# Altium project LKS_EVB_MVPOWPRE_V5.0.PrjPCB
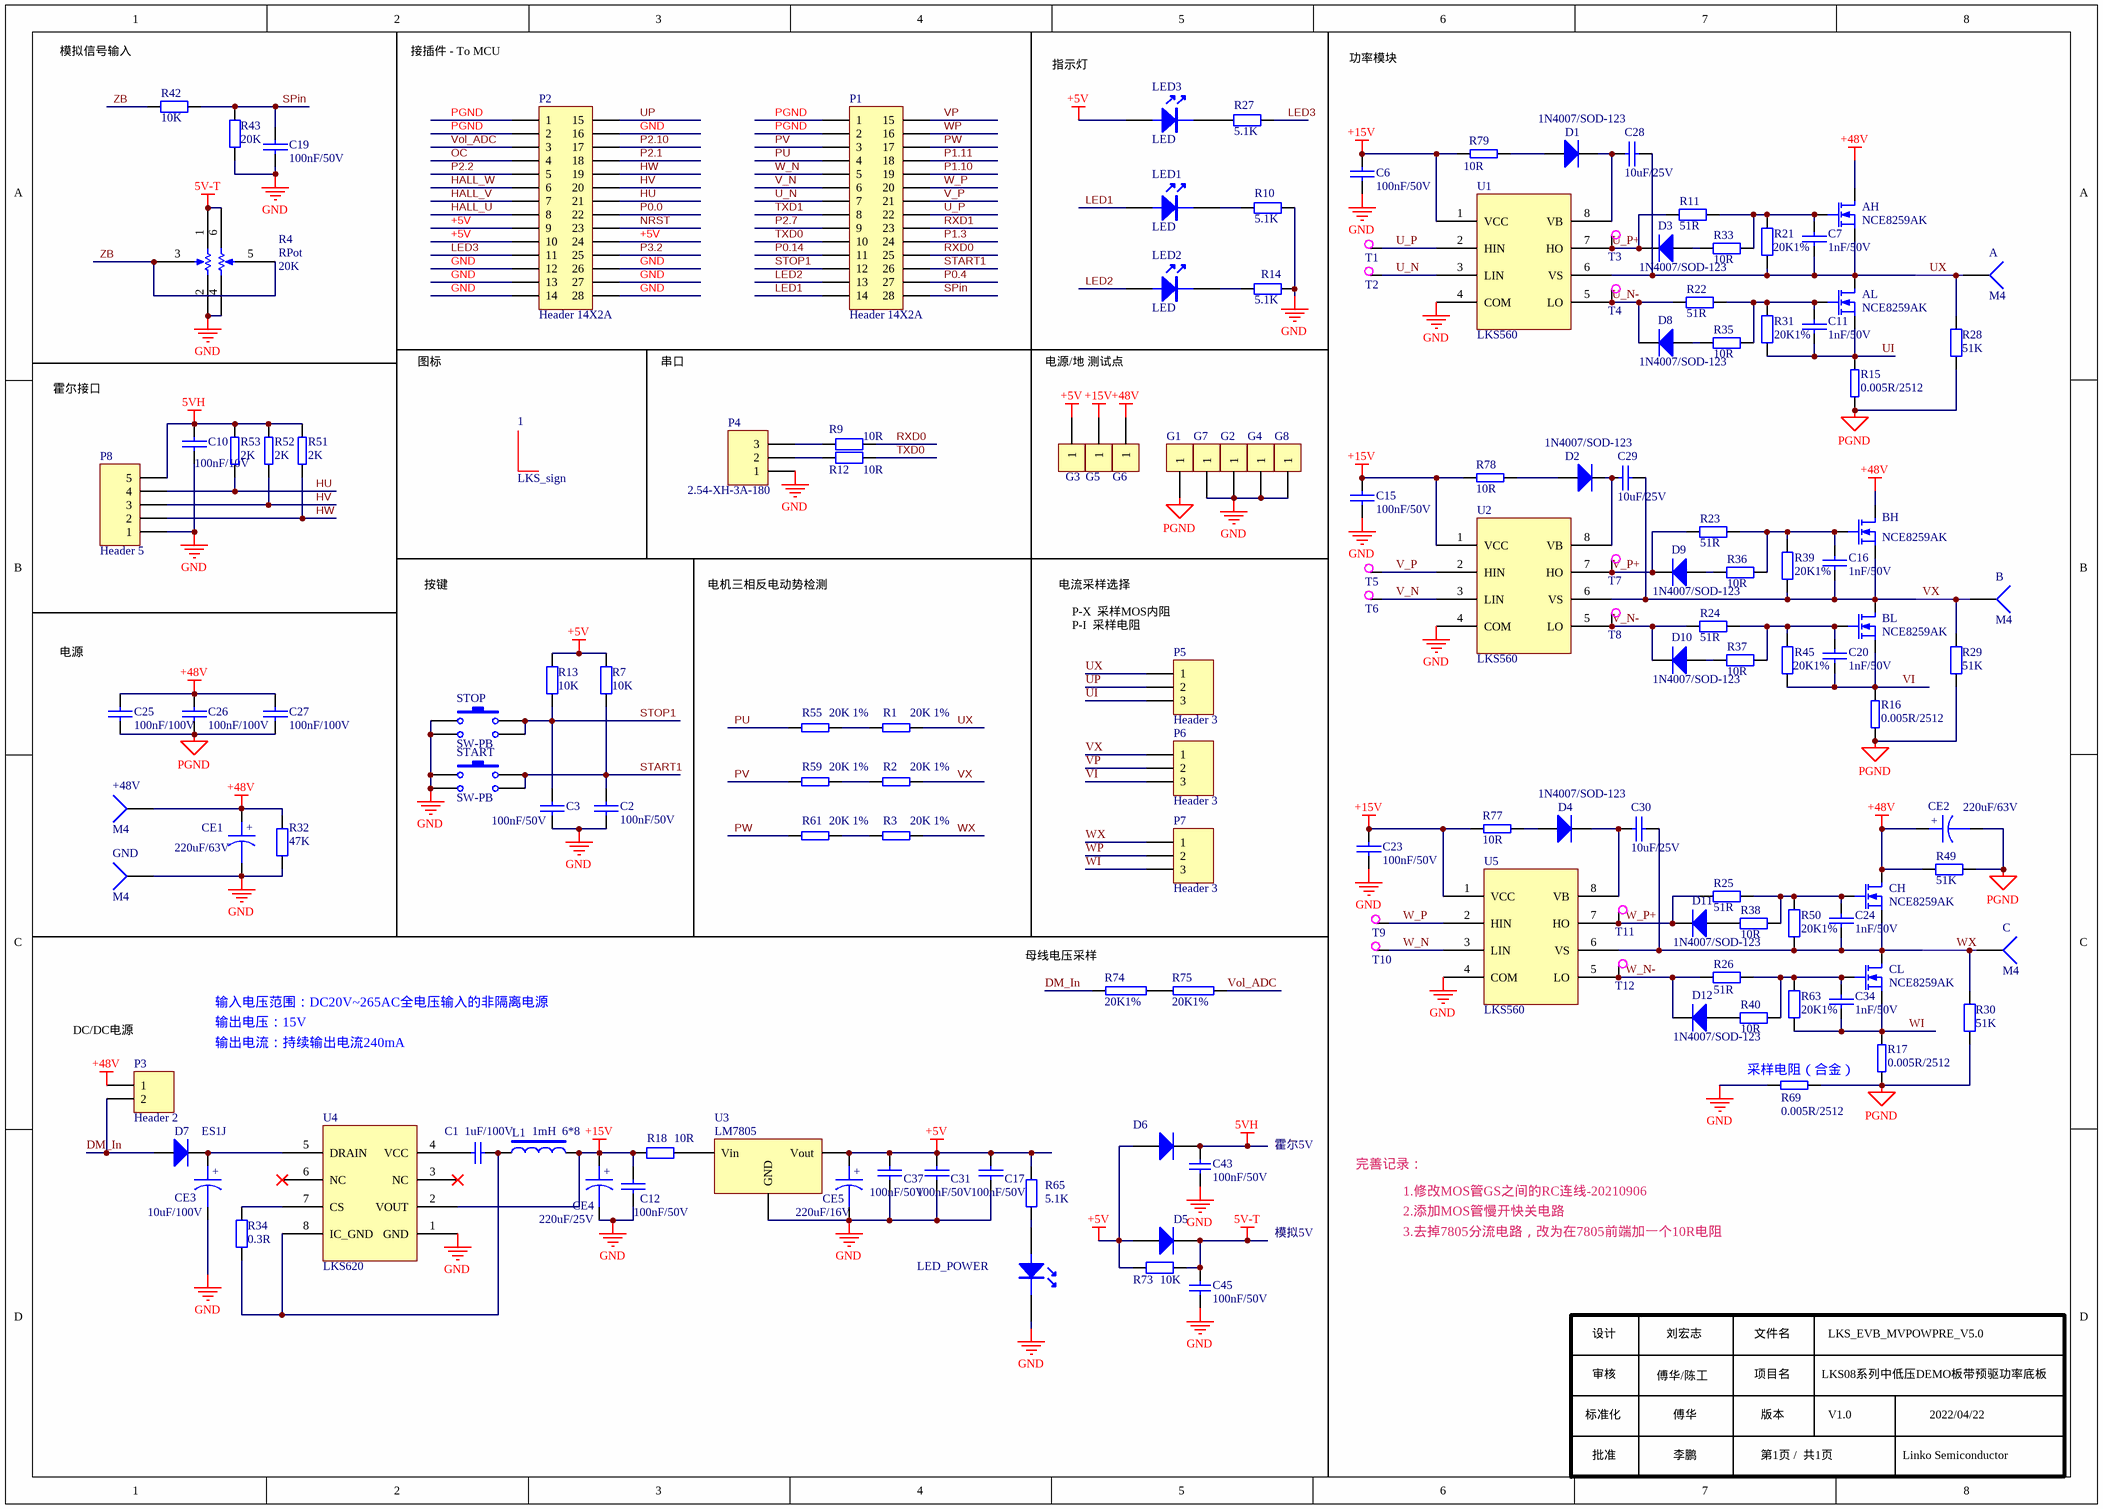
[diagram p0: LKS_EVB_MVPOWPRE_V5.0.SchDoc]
1 sheet, 150 parts. Net scope: global (net labels, ports and power ports of the same name join across sheets).
Board file: LKS_EVB_MVPOWPRE_V5.0.PcbDoc

## Sheet LKS_EVB_MVPOWPRE_V5.0.SchDoc: LKS_DEMO_V4.0
size A3; Author: LKS_LHZ

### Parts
1  LKS_sign  [LKS_LOGO2]
+48V  M4  [M4_CONECTOR]
A  M4  [M4_Conector]
AH  NCE8259AK  [TO-252]
AL  NCE8259AK  [TO-252]
B  M4  [M4_Conector]
BH  NCE8259AK  [TO-252]
BL  NCE8259AK  [TO-252]
C  M4  [M4_Conector]
C1  1uF/100V  [1206]
C2  100nF/50V  [0603C]
C3  100nF/50V  [0603C]
C6  100nF/50V  [0603C]
C7  1nF/50V  [0603C]
C10  100nF/10V  [0603C]
C11  1nF/50V  [0603C]
C12  100nF/50V  [0603C]
C15  100nF/50V  [0603C]
C16  1nF/50V  [0603C]
C17  100nF/50V  [0603C]
C19  100nF/50V  [0603C]
C20  1nF/50V  [0603C]
C23  100nF/50V  [0603C]
C24  1nF/50V  [0603C]
C25  100nF/100V  [0805C]
C26  100nF/100V  [0805C]
C27  100nF/100V  [0805C]
C28  10uF/25V  [1206C]
C29  10uF/25V  [1206C]
C30  10uF/25V  [1206C]
C31  100nF/50V  [0603C]
C34  1nF/50V  [0603C]
C37  100nF/50V  [0603C]
C43  100nF/50V  [0603C]
C45  100nF/50V  [0603C]
CE1  220uF/63V  [220UF/63V 12.5*12.5]
CE2  220uF/63V  [220UF/63V 12.5*12.5]
CE3  10uF/100V  [220UF/25V 8*10]
CE4  220uF/25V  [220UF/25V 8*10]
CE5  220uF/16V  [220UF/25V 8*10]
CH  NCE8259AK  [TO-252]
CL  NCE8259AK  [TO-252]
D1  1N4007/SOD-123  [SOD123]
D2  1N4007/SOD-123  [SOD123]
D3  1N4007/SOD-123  [SOD123]
D4  1N4007/SOD-123  [SOD123]
D5  1N4007  [D1206]  (value not drawn)
D6  1N4007  [D1206]  (value not drawn)
D7  ES1J  [DO-214AC]
D8  1N4007/SOD-123  [SOD123]
D9  1N4007/SOD-123  [SOD123]
D10  1N4007/SOD-123  [SOD123]
D11  1N4007/SOD-123  [SOD123]
D12  1N4007/SOD-123  [SOD123]
G1  PAD1.2  [PAD1.2]  (value not drawn)
G2  PAD1.2  [PAD1.2]  (value not drawn)
G3  PAD1.2  [PAD1.2]  (value not drawn)
G4  PAD1.2  [PAD1.2]  (value not drawn)
G5  PAD1.2  [PAD1.2]  (value not drawn)
G6  PAD1.2  [PAD1.2]  (value not drawn)
G7  PAD1.2  [PAD1.2]  (value not drawn)
G8  PAD1.2  [PAD1.2]  (value not drawn)
GND  M4  [M4_CONECTOR]
L1  1mH  6*8  [L_DIP_6*8MM]
LED1  LED  [SOD323]
LED2  LED  [SOD323]
LED3  LED  [SOD323]
LED_POWER  LED_R  [SOD323]  (value not drawn)
P1  Header 14X2A  [HDR2X14_CEN]
P2  Header 14X2A  [HDR2X14_CEN]
P3  Header 2  [HDR1X2]
P4  2.54-XH-3A-180  [2.54-XH-3A-180]
P5  Header 3  [HDR1X3]
P6  Header 3  [HDR1X3]
P7  Header 3  [HDR1X3]
P8  Header 5  [2.54-XH-5A-180]
R1  20K 1%  [0805R]
R2  20K 1%  [0805R]
R3  20K 1%  [0805R]
R4  RPot  value 20K  [RK097-W-1]
R7  10K  [0603R]
R9  10R  [0603R]
R10  5.1K  [0603R]
R11  51R  [0805R]
R12  10R  [0603R]
R13  10K  [0603R]
R14  5.1K  [0603R]
R15  0.005R/2512  [2512]
R16  0.005R/2512  [2512]
R17  0.005R/2512  [2512]
R18  10R  [1206R]
R21  20K1%  [0603R]
R22  51R  [0805R]
R23  51R  [0805R]
R24  51R  [0805R]
R25  51R  [0805R]
R26  51R  [0805R]
R27  5.1K  [0603R]
R28  51K  [0805R]
R29  51K  [0805R]
R30  51K  [0805R]
R31  20K1%  [0603R]
R32  47K  [1206R]
R33  10R  [0805R]
R34  0.3R  [1206]
R35  10R  [0805R]
R36  10R  [0805R]
R37  10R  [0805R]
R38  10R  [0805R]
R39  20K1%  [0603R]
R40  10R  [0805R]
R42  10K  [0603R]
R43  20K  [0603R]
R45  20K1%  [0603R]
R49  51K  [0805R]
R50  20K1%  [0603R]
R51  2K  [0805R]
R52  2K  [0805R]
R53  2K  [0805R]
R55  20K 1%  [0805R]
R59  20K 1%  [0805R]
R61  20K 1%  [0805R]
R63  20K1%  [0603R]
R65  5.1K  [0603R]
R69  0.005R/2512  [2512]
R73  10K  [0603R]
R74  20K1%  [0603R]
R75  20K1%  [0603R]
R77  10R  [0805r]
R78  10R  [0805r]
R79  10R  [0805r]
START  SW-PB  [SW-PB  12*12]
STOP  SW-PB  [SW-PB  12*12]
T1  TestP  [TP-80]  (value not drawn)
T2  TestP  [TP-80]  (value not drawn)
T3  TestP  [TP-80]  (value not drawn)
T4  TestP  [TP-80]  (value not drawn)
T5  TestP  [TP-80]  (value not drawn)
T6  TestP  [TP-80]  (value not drawn)
T7  TestP  [TP-80]  (value not drawn)
T8  TestP  [TP-80]  (value not drawn)
T9  TestP  [TP-80]  (value not drawn)
T10  TestP  [TP-80]  (value not drawn)
T11  TestP  [TP-80]  (value not drawn)
T12  TestP  [TP-80]  (value not drawn)
U1  LKS560  [SO-8]
U2  LKS560  [SO-8]
U3  LM7805  [SOT-89]
U4  LKS620  [SO-8]
U5  LKS560  [SO-8]

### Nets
5V-T: C45.2 D5.2(K) R4.1(TOP) R4.6(TOP) R73.2
5VH: C10.1 C43.2 D6.2(K) P8.5 R51.2 R52.2 R53.2
+5V: C17.2 C31.2 C37.2 CE5.1 D5.1(A) D6.1(A) G3.1 LED3.1(A) P2.9 P2.10 P2.24 R7.1 R13.2 R65.1 R73.1 U3.1(Vout)
+15V: C6.2 C12.1 C15.2 C23.2 CE4.1 G5.1 L1.1 R18.1 R77.1 R78.1 R79.1 U1.1(VCC) U2.1(VCC) U4.2(VOUT) U5.1(VCC)
+48V: +48V.1 AH.2(D) BH.2(D) C25.2 C26.2 C27.2 CE1.1 CE2.1 CH.2(D) G6.1 P3.1 R32.1 R49.1
GND: C2.1 C3.2 C6.1 C10.2 C12.2 C15.1 C17.1 C19.1 C23.1 C31.1 C37.1 C43.1 C45.1 CE1.2 CE3.2 CE4.2 CE5.2 G2.1 G4.1 G7.1 G8.1 GND.1 LED_POWER.2(K) P2.12 P2.13 P2.14 P2.16 P2.26 P2.27 P2.28 P4.1 P8.1 R4.2(TAP) R4.4(BOT) R10.2 R14.2 R32.2 R43.1 R69.2 START.1 START.3 STOP.1 STOP.3 U1.4(COM) U2.4(COM) U3.2(GND) U4.1(GND) U5.4(COM)
PGND: C25.1 C26.1 C27.1 CE2.2 G1.1 P1.1 P1.2 P2.1 P2.2 R15.2 R16.1 R17.2 R28.1 R29.1 R30.1 R49.2 R69.1
DM_In: D7.1(A) P3.2 R74.1
HALL_U: P2.8
HALL_V: P2.7
HALL_W: P2.6
HU: P2.21 P8.4 R53.1
HV: P2.20 P8.3 R52.1
HW: P2.19 P8.2 R51.1
LED1: LED1.1(A) P1.14
LED2: LED2.1(A) P1.13
LED3: P2.11 R27.2
NRST: P2.23
OC: P2.4
P0.0: P2.22
P0.4: P1.27
P0.14: P1.11
P1.3: P1.24
P1.10: P1.19
P1.11: P1.18
P2.1: P2.18
P2.2: P2.5
P2.7: P1.9
P2.10: P2.17
P3.2: P2.25
PU: P1.4 R55.1
PV: P1.3 R59.1
PW: P1.17 R61.1
RXD0: P1.25 R9.1
RXD1: P1.23
SPin: C19.2 P1.28 R42.2 R43.2
START1: C2.2 P1.26 R7.2 START.2 START.4
STOP1: C3.1 P1.12 R13.1 STOP.2 STOP.4
TXD0: P1.10 R12.2
TXD1: P1.8
U_N: P1.7 T2.1 U1.3(LIN)
U_N-: D8.2(K) R22.2 T4.1 U1.5(LO)
U_P: P1.22 T1.1 U1.2(HIN)
U_P+: D3.2(K) R11.1 T3.1 U1.7(HO)
UI: AL.3(S) C11.2 P5.3 R15.1 R31.1
UP: P2.15 P5.2
UX: A.1 AH.3(S) AL.2(D) C7.2 C28.2 P5.1 R1.2 R21.1 R28.2 U1.6(VS)
V_N: P1.6 T6.1 U2.3(LIN)
V_N-: D10.2(K) R24.2 T8.1 U2.5(LO)
V_P: P1.21 T5.1 U2.2(HIN)
V_P+: D9.2(K) R23.1 T7.1 U2.7(HO)
VI: BL.3(S) C20.2 P6.3 R16.2 R45.1
Vol_ADC: P2.3 R75.2
VP: P1.15 P6.2
VX: B.1 BH.3(S) BL.2(D) C16.2 C29.2 P6.1 R2.2 R29.2 R39.1 U2.6(VS)
W_N: P1.5 T10.1 U5.3(LIN)
W_N-: D12.2(K) R26.2 T12.1 U5.5(LO)
W_P: P1.20 T9.1 U5.2(HIN)
W_P+: D11.2(K) R25.1 T11.1 U5.7(HO)
WI: C34.2 CL.3(S) P7.3 R17.1 R63.1
WP: P1.16 P7.2
WX: C.1 C24.2 C30.2 CH.3(S) CL.2(D) P7.1 R3.2 R30.2 R50.1 U5.6(VS)
ZB: R4.3(BOT) R4.5(TAP) R42.1
NetAH_1: AH.1(G) C7.1 R11.2 R21.2 R33.2
NetAL_1: AL.1(G) C11.1 R22.1 R31.2 R35.2
NetBH_1: BH.1(G) C16.1 R23.2 R36.2 R39.2
NetBL_1: BL.1(G) C20.1 R24.1 R37.2 R45.2
NetC1_1: C1.1 U4.4(VCC)
NetC1_2: C1.2 L1.2 R34.2 U4.8(IC_GND)
NetC24_1: C24.1 CH.1(G) R25.2 R38.2 R50.2
NetC28_1: C28.1 D1.2(K) U1.8(VB)
NetC29_1: C29.1 D2.2(K) U2.8(VB)
NetC30_1: C30.1 D4.2(K) U5.8(VB)
NetC34_1: C34.1 CL.1(G) R26.1 R40.2 R63.2
NetCE3_1: CE3.1 D7.2(K) U4.5(DRAIN)
NetD1_1: D1.1(A) R79.2
NetD2_1: D2.1(A) R78.2
NetD3_1: D3.1(A) R33.1
NetD4_1: D4.1(A) R77.2
NetD8_1: D8.1(A) R35.1
NetD9_1: D9.1(A) R36.1
NetD10_1: D10.1(A) R37.1
NetD11_1: D11.1(A) R38.1
NetD12_1: D12.1(A) R40.1
NetLED1_2: LED1.2(K) R10.1
NetLED2_2: LED2.2(K) R14.1
NetLED3_2: LED3.2(K) R27.1
NetLED_POWER_1: LED_POWER.1(A) R65.2
NetP4_2: P4.2 R12.1
NetP4_3: P4.3 R9.2
NetR1_1: R1.1 R55.2
NetR2_1: R2.1 R59.2
NetR3_1: R3.1 R61.2
NetR18_2: R18.2 U3.3(Vin)
NetR34_1: R34.1 U4.7(CS)
NetR74_2: R74.2 R75.1

Not connected (* = marked no-connect by the designer): U4 3(NC)* 6(NC)*

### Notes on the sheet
- 模拟信号输入
- 接插件 - To MCU
- 指示灯
- 功率模块
- 图标
- 串口
- 电源/地 测试点
- 霍尔接口
- 按键
- 电机三相反电动势检测
- 电流采样选择
- P-X  采样MOS内阻
- P-I  采样电阻
- 电源
- (near R74) 母线电压采样
- (near P3) DC/DC电源
- 输入电压范围：DC20V|65AC全电压输入的非隔离电源
- 输出电压：15V
- 输出电流：持续输出电流240mA
- (near R69) 采样电阻（合金）
- 完善记录：
- 1.修改MOS管GS之间的RC连线-20210906
- 2.添加MOS管慢开快关电路
- 3.去掉7805分流电路，改为在7805前端加一个10R电阻
- 设计
- 审核
- 傅华/陈工
- 刘宏志
- 文件名
- 项目名
- LKS08系列中低压DEMO板带预驱功率底板
- LKS_EVB_MVPOWPRE_V5.0
- 标准化
- 批准
- 傅华
- 李鹏
- 版本
- 第1页 /  共1页
- V1.0
- Linko Semiconductor
- 2022/04/22
- Labels drawn without touching a wire or pin: 模拟5V, 霍尔5V

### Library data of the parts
+48V A B C GND = Socket
AH AL BH BL CH CL = MOS
C1 = Cap: Capacitor; Value: 10uF/100V
C2 C3 C7 C10-C12 C16 C20 C24-C27 C34 = CAP: Capacitor
C6 C15 C17 C19 C23 C31 C37 = C: Capacitor
C28-C30 = Capacitor: Capacitor --贴片电容
C43 C45 = Cap: Capacitor; Value: 104
CE1-CE5 = Capacitor Pol: Capacitor---电解电容
D1-D4 D7-D12 = Diode: Default Diode
D5 D6 = Diode 1N4007: 1 Amp General Purpose Rectifier
G1-G8 = CON1: Connector
L1 = L
LED_POWER = LED
P1 P2 = Header 14X2A: Header, 14-Pin, Dual row
P3 = Header 2: Header, 2-Pin
P4-P7 = Header 3: Header, 3-Pin
P8 = Header 5: Header, 5-Pin
R1-R3 R51-R53 R55 R59 R61 = RES/1
R4 = RPot: Potentiometer; Sim Note: Enter the Resistance value and the set point into parameter fields.; Set Position: 0.5
R7 R9 R13 R34 R73 = Res2: Resistor
R10 R14 R27 = Res2: Resistor; Value: 10K
R11 R18 R21-R26 R31-R33 R39 R42 R43 R45 R50 R63 = Res: Resistor; Value: K
R12 = Res2: Resistor; Value: 100R
R15-R17 R69 R77-R79 = RES2短
R28-R30 R35-R38 R40 R49 = 1Res: Resistor; Value: K
R65 = Res2: Resistor; Value: 510R
R74 R75 = R
START STOP = SW-PB: Switch
U1 U2 U5 = IRS2003S
U3 = VOL-78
